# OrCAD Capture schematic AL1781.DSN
size Custom; title: AL1781, Single/Dual Dimmable Linear LED Driver; rev: 1.0; note: DS41312 Rev. 1 - 2
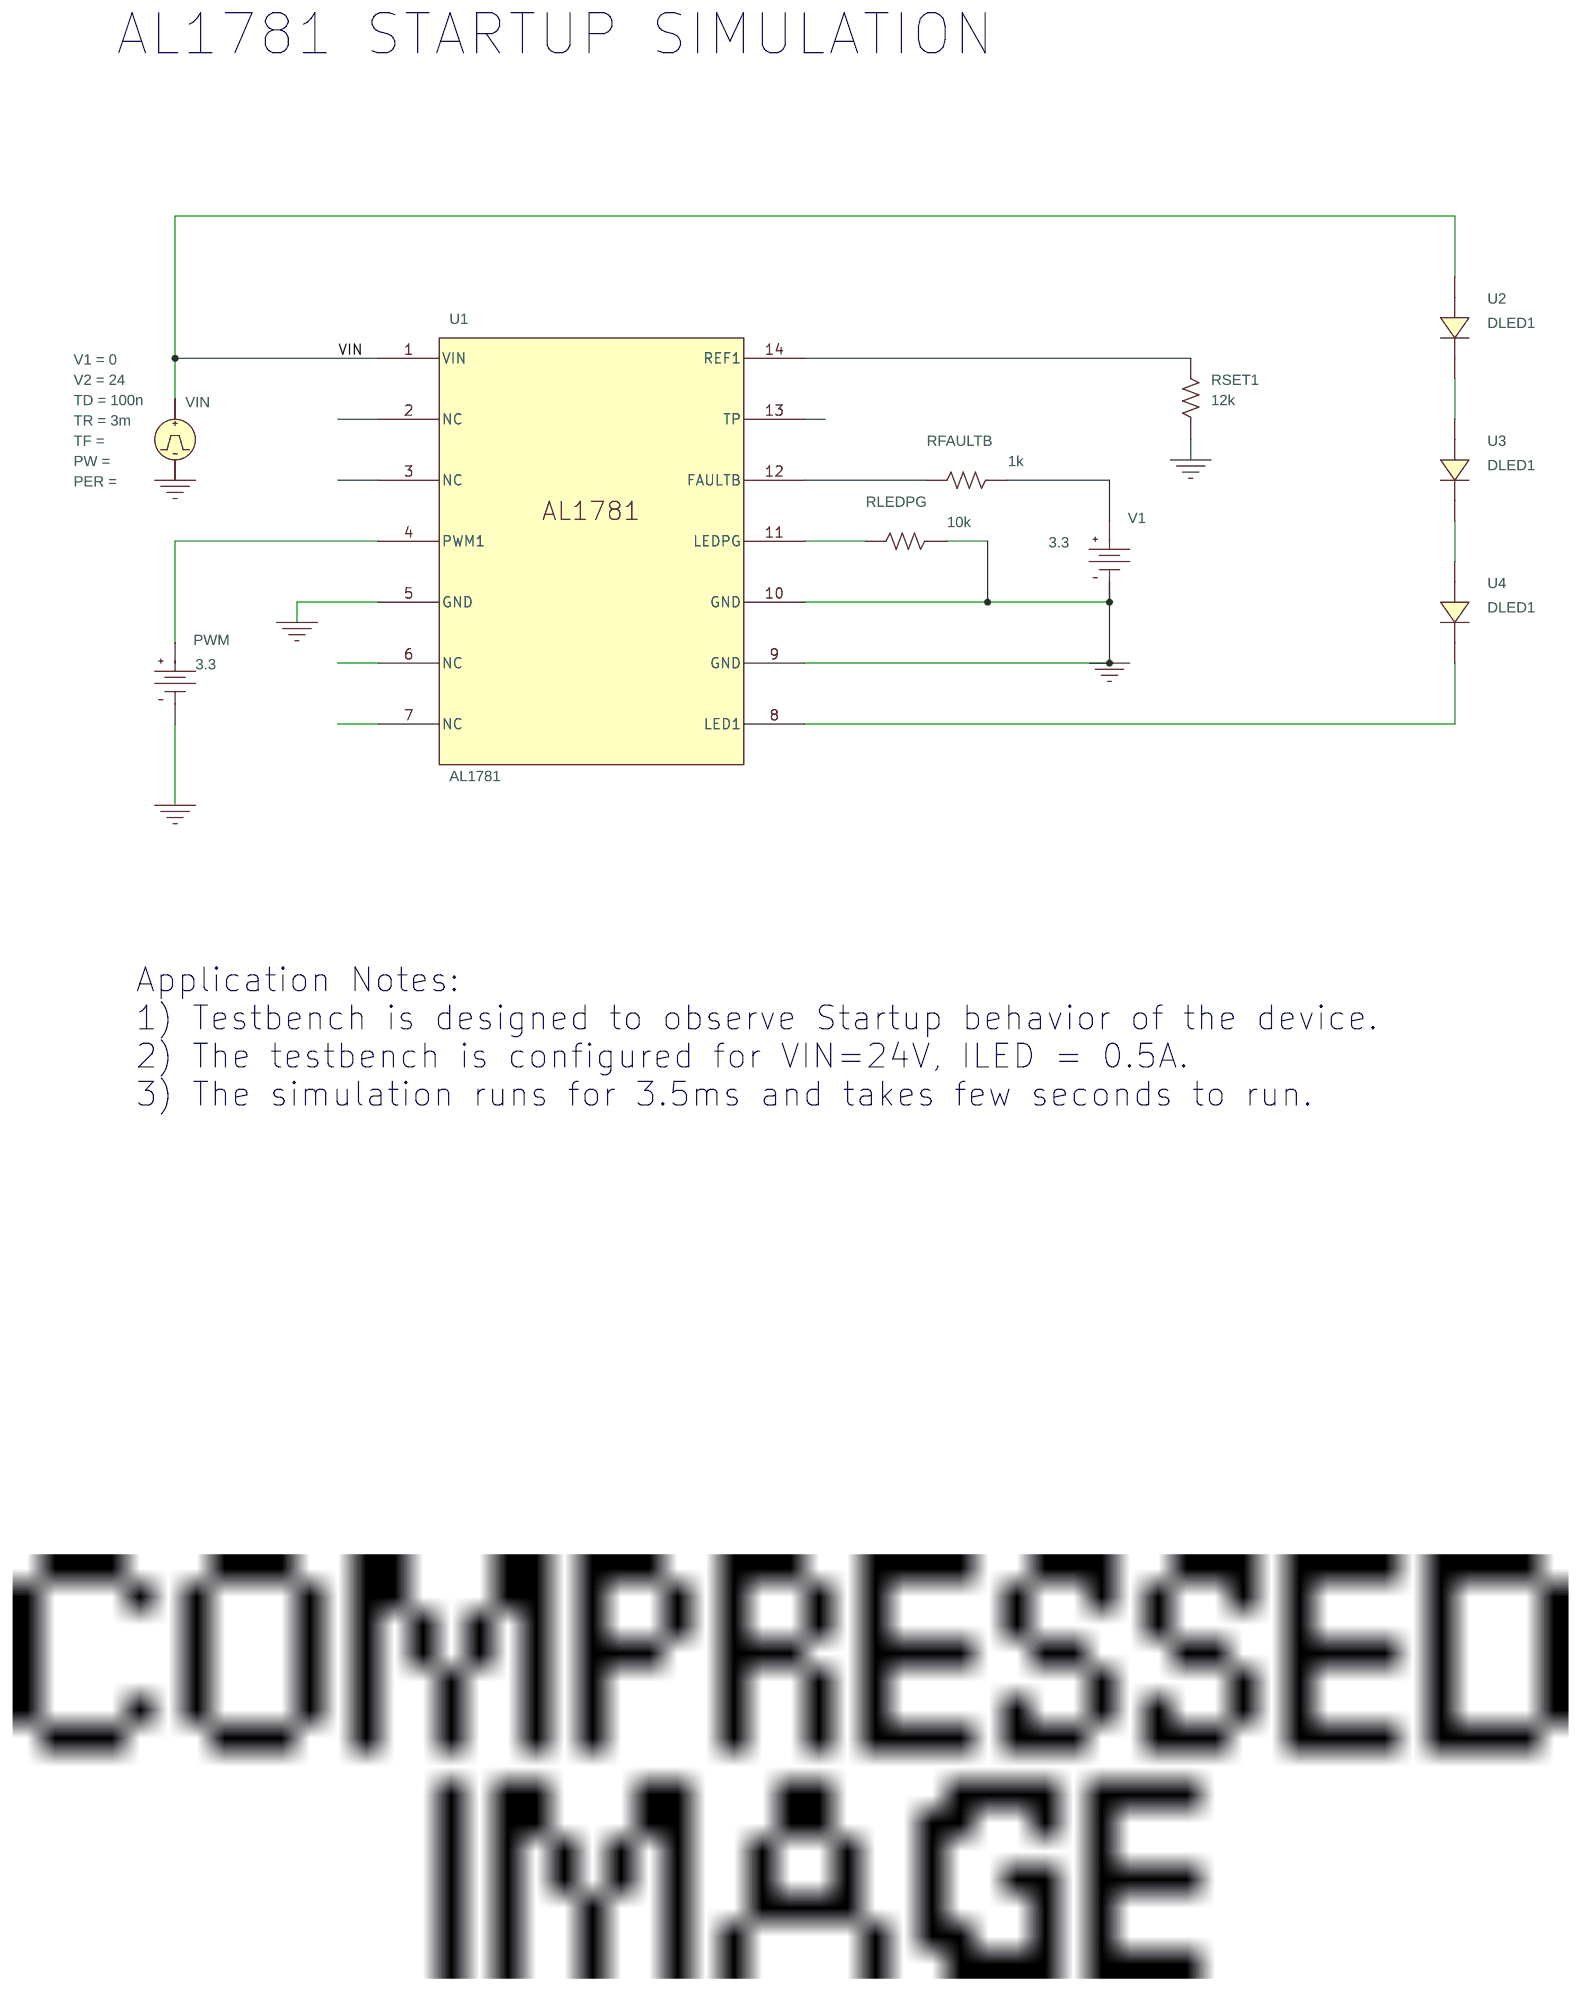
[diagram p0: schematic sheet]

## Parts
PWM  VDC
RFAULTB  1k  [AX/RC05]
RLEDPG  10k  [AX/RC05]
RSET1  12k  [AX/RC05]
U1  AL1781
U2  DLED1
U3  DLED1
U4  DLED1
V1  VDC
VIN  VPULSE

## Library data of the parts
PWM V1 = VDC: DC: 3.3
RFAULTB RLEDPG RSET1 = R
U1 = AL1781: PSpiceTemplate: X^@REFDES %VIN %NC %NC %PWM1 %GND %NC %NC %LED1 %GND %GND %LEDPG %FAULTB %TP %REF1 @MODEL
U2-U4 = DLED1
VIN = VPULSE: TD: 100n; TR: 3m; V1: 0; V2: 24

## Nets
VIN: U1.1(VIN) U2.1 VIN.1(+)
0: PWM.1(-) RLEDPG.1 RSET1.1 U1.5(GND) U1.9(GND) U1.10(GND) V1.1(-) VIN.2(-)
N245727: PWM.0(+) U1.4(PWM1)
N245733: U2.2 U3.1
N245829: U1.8(LED1) U4.2
N245835: U3.2 U4.1
N245885: RLEDPG.2 U1.11(LEDPG)
N245927: RFAULTB.2 U1.12(FAULTB)
N245951: RSET1.2 U1.14(REF1)
N245981: RFAULTB.1 V1.0(+)

Not connected (* = marked no-connect by the designer): U1 2(NC) 3(NC) 6(NC) 7(NC) 13(TP)

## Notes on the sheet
- AL1781 STARTUP SIMULATION
- Application Notes:
  1) Testbench is designed to observe Startup behavior of the device.
  2) The testbench is configured for VIN=24V, ILED = 0.5A.
  3) The simulation runs for 3.5ms and takes few seconds to run.
